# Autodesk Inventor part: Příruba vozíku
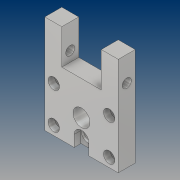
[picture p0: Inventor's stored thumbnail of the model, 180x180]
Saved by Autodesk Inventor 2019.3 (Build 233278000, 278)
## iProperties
Created: 2019-01
Part Number: Příruba vozíku
Material: Hliník 6061-AHC
Document SubType Name: Modeling
Designer: B-hon
Density: 2.7 g/cm^3
Appearance: Hliník – tmavý
Author: B-hon
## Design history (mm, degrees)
sketch "Náčrt1"
  geometry: L1 (-24.5, 16)-(24.5, 16); L2 (24.5, 16)-(24.5, -16); L3 (24.5, -16)-(-24.5, -16); L4 (-24.5, -16)-(-24.5, 16); L5 (-24.5, 16)-(24.5, -16); L6 (24.5, 16)-(-24.5, -16); L7 (32.5, -24)-(-32.5, -24); L8 (-32.5, -24)-(-32.5, 56); L9 (32.5, 56)-(32.5, -24); L10 (-32.5, 56)-(32.5, 56); 1 further point
  constraints: 20 end point, 3 horizontal, 3 parallel, 2 midpoint, 2 perpendicular
  dimensions: "d0" = 49 distance of L2.end L3.end; "d1" = 32 distance of L1.end L2.end; "d4" = 80 distance between parallel lines of L7 L10; "d21" = 8 distance between parallel lines of L9 L2; "d22" = 8 distance between parallel lines of L4 L8; "d23" = 8 distance between parallel lines of L7 L3
extrude "Vysunutí1" new body sketch "Náčrt1" distance "d5" = 12; taper "d6" = 0 deg
sketch "Náčrt2"
  geometry: L1 (0, 80)-(0, 0) reference; L2 (0, 0)-(-12, 0) reference; 2 further points
  dimensions: "d7" = 4.5 distance from line of L1 point (-4.5, 65); "d8" = 65 distance from line of L2 point (-4.5, 65)
hole "Díra1" sketch "Náčrt2" at (-4.5, 65) diameter "d9" = 8; stored, may be unused: countersink angle "d13" = 90 deg, drill point angle "d15" = 118 deg; dims "d10" = 6, "d11" = 4, "d12" = 2, "d14" = 8
sketch "Náčrt3"
  geometry: L1 (32.5, 56)-(-32.5, 56) reference; L2 (-17.5, 56)-(17.5, 56); L3 (17.5, 56)-(17.5, 32); L4 (17.5, 32)-(-17.5, 32); L5 (-17.5, 32)-(-17.5, 56); L6 (-32.5, -24)-(32.5, -24) reference; 1 further point
  constraints: 8 end point, 2 parallel, 1 horizontal, 1 perpendicular, 1 point on line
  dimensions: "d16" = 56 distance between parallel lines of L4 L6; "d17" = 35 distance of L3.end L4.end; "d18" = 15 distance from line of L1.end L5
extrude "Vysunutí2" cut sketch "Náčrt3" distance "d19" = 12; taper "d20" = 0 deg
sketch "Náčrt5"
  geometry: L1 (-24.5, 16)-(24.5, 16); L2 (24.5, 16)-(24.5, -16); L3 (24.5, -16)-(-24.5, -16); L4 (-24.5, -16)-(-24.5, 16); L5 (-24.5, 16)-(24.5, -16); L6 (24.5, 16)-(-24.5, -16); 5 further points
  constraints: 12 end point, 4 coincident, 2 midpoint, 2 parallel, 1 horizontal, 1 perpendicular
  dimensions: "d24" = 49 distance of L2.end L3.end; "d25" = 32 distance of L1.end L2.end
hole "Díra2" sketch "Náčrt5" at (-24.5, 16), (24.5, 16), (24.5, -16), (-24.5, -16) diameter "d26" = 5.3; stored, may be unused: countersink angle "d30" = 90 deg, drill point angle "d32" = 118 deg; dims "d27" = 6, "d28" = 10, "d29" = 5.7, "d31" = 8
node "Upravit přímo1"
sketch "Náčrt6"
  geometry: L1 (-32.5, -24)-(32.5, -24) reference; C1 r 6.5 at (0, -14); 1 further point
  constraints: 1 centre point
  dimensions: "d36" = 13 diameter of C1; "d37" = 10 distance from line of L1 C1.centre
extrude "Vysunutí3" cut sketch "Náčrt6" distance "d38" = 8; taper "d39" = 0 deg
sketch "Náčrt7"
  geometry: L1 (6.5, -48.468)-(-6.5, -48.468); L2 (-6.5, -48.468)-(-6.5, -14); L3 (-6.5, -14)-(6.5, -14); L4 (6.5, -14)-(6.5, -48.468); L5 (6.5, -48.468)-(-6.5, -14); L6 (-6.5, -48.468)-(6.5, -14); 3 further points
  constraints: 12 end point, 2 midpoint, 2 parallel, 1 horizontal, 1 horizontal alignment, 1 perpendicular, 1 other
  dimensions: "d40" = 13 distance of L2.end L3.end
extrude "Vysunutí4" cut sketch "Náčrt7" distance "d41" = 6; taper "d42" = 0 deg
node "Upravit přímo2"
sketch "Náčrt8"
  geometry: L1 (-32.5, -24)-(-6.5, -24) reference; L2 (-32.5, 63)-(-32.5, -24) reference; 2 further points
  dimensions: "d46" = 26 distance from line of L1 point (0, 2); "d47" = 32.5 distance from line of L2 point (0, 2)
hole "Díra3" sketch "Náčrt8" at (0, 2) diameter "d48" = 15; stored, may be unused: countersink angle "d52" = 90 deg, drill point angle "d54" = 118 deg; dims "d49" = 6, "d50" = 4, "d51" = 2, "d53" = 13
node "Těleso1"
feature "Posunout1" dims "d35" = 7
feature "Posunout2" dims "d45" = 3
other parameters: "d33" = 0, "d34" = 0, "d43" = 0, "d44" = 0
